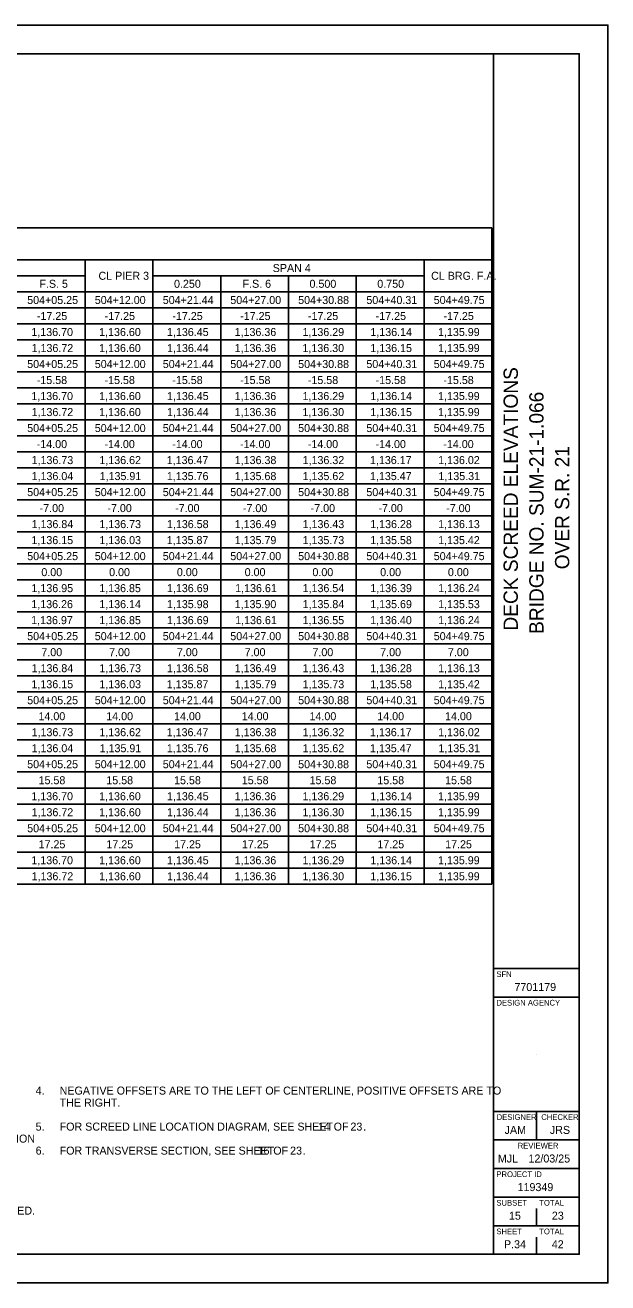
# Model space of a CAD drawing. Extents: x 0 to 34, y 0 to 22.
# Drawn here: x 23.8 to 34, y 0 to 22 of the extents above; entities that cross this region are included whole.
import ezdxf

# ---------------------------------------------------------------- set-up
doc = ezdxf.new("R2010")
doc.units = 0
for name, color, linetype in [('BR_P_Gen_Text', 7, 'Continuous'), ('Default', 7, 'Continuous'), ('SH_Border', 7, 'Continuous'), ('SH_Cut_Line', 7, 'Continuous'), ('SH_Data', 7, 'Continuous')]:
    doc.layers.add(name, color=color, linetype=linetype)

msp = doc.modelspace()

# ---------------------------------------------------------------- linework, layer by layer
at = {"layer": 'Default'}
for p, q in [((1.531, 18.456), (31.969, 18.456)), ((31.969, 18.456), (31.969, 6.976)), ((1.531, 17.896), (31.969, 17.896)), ((24.854, 17.896), (24.854, 6.976)), ((26.039, 17.896), (26.039, 6.976)), ((30.783, 17.896), (30.783, 6.976)), ((18.924, 17.616), (24.854, 17.616)), ((26.039, 17.616), (30.783, 17.616)), ((27.225, 17.616), (27.225, 6.976)), ((28.411, 17.616), (28.411, 6.976)), ((29.597, 17.616), (29.597, 6.976)), ((1.531, 17.336), (31.969, 17.336)), ((2.585, 17.056), (31.969, 17.056)), ((2.585, 16.776), (31.969, 16.776)), ((2.585, 16.496), (31.969, 16.496)), ((1.531, 16.216), (31.969, 16.216)), ((2.585, 15.936), (31.969, 15.936)), ((2.585, 15.656), (31.969, 15.656)), ((2.585, 15.376), (31.969, 15.376)), ((1.531, 15.096), (31.969, 15.096)), ((2.585, 14.816), (31.969, 14.816)), ((2.585, 14.536), (31.969, 14.536)), ((2.585, 14.256), (31.969, 14.256)), ((1.531, 13.976), (31.969, 13.976)), ((2.585, 13.696), (31.969, 13.696)), ((2.585, 13.416), (31.969, 13.416)), ((2.585, 13.136), (31.969, 13.136)), ((1.531, 12.856), (31.969, 12.856)), ((2.585, 12.576), (31.969, 12.576)), ((2.585, 12.296), (31.969, 12.296)), ((2.585, 12.016), (31.969, 12.016)), ((2.585, 11.736), (31.969, 11.736)), ((1.531, 11.456), (31.969, 11.456)), ((2.585, 11.176), (31.969, 11.176)), ((2.585, 10.896), (31.969, 10.896)), ((2.585, 10.616), (31.969, 10.616)), ((1.531, 10.336), (31.969, 10.336)), ((2.585, 10.056), (31.969, 10.056)), ((2.585, 9.776), (31.969, 9.776)), ((2.585, 9.496), (31.969, 9.496)), ((1.531, 9.216), (31.969, 9.216)), ((2.585, 8.936), (31.969, 8.936)), ((2.585, 8.656), (31.969, 8.656)), ((2.585, 8.376), (31.969, 8.376)), ((1.531, 8.096), (31.969, 8.096)), ((2.585, 7.816), (31.969, 7.816)), ((2.585, 7.536), (31.969, 7.536)), ((2.585, 7.256), (31.969, 7.256)), ((1.531, 6.976), (31.969, 6.976))]:
    msp.add_line(p, q, dxfattribs=at)
at = {"layer": 'SH_Border'}
for p, q in [((32, 0.5), (32, 21.5)), ((32, 5.5), (33.5, 5.5)), ((32, 5), (33.5, 5)), ((32, 3), (33.5, 3)), ((32.75, 3), (32.75, 2.5)), ((32, 2.5), (33.5, 2.5)), ((32, 2), (33.5, 2)), ((32, 1.5), (33.5, 1.5)), ((32, 1), (33.5, 1))]:
    msp.add_line(p, q, dxfattribs=at)
msp.add_lwpolyline([(1.5, 21.5), (33.5, 21.5), (33.5, 0.5), (1.5, 0.5)], close=True, dxfattribs=at)
at = {"layer": 'SH_Cut_Line'}
msp.add_lwpolyline([(0, 0), (34, 0), (34, 22), (0, 22)], close=True, dxfattribs=at)
at = {"layer": 'SH_Data'}
for p, q in [((32.75, 4), (32.75, 4)), ((32.75, 1), (32.75, 1.3)), ((32.375, 0.675), (32.375, 0.675)), ((32.75, 0.5), (32.75, 0.8))]:
    msp.add_line(p, q, dxfattribs=at)

# ---------------------------------------------------------------- texts
at = {"layer": 'BR_P_Gen_Text'}
for s, p in [('4.', (23.986, 3.293)), ('NEGATIVE OFFSETS ARE TO THE LEFT OF CENTERLINE, POSITIVE OFFSETS ARE TO ', (24.406, 3.293)), ('THE RIGHT.', (24.406, 3.083)), ('5.', (23.986, 2.663)), ('FOR SCREED LINE LOCATION DIAGRAM, SEE SHEET ', (24.406, 2.663)), ('14', (28.926, 2.663)), (' OF ', (29.15, 2.663)), ('23', (29.495, 2.663)), ('.', (29.718, 2.663)), ('TOP OF HAUNCH ELEVATIONS SHOWN REPRESENT THE THEORETICAL LOCATION ', (16.434, 2.453)), ('6.', (23.986, 2.243)), ('FOR TRANSVERSE SECTION, SEE SHEET', (24.406, 2.243)), ('16', (27.87, 2.243)), (' OF ', (28.093, 2.243)), ('23', (28.439, 2.243)), ('.', (28.662, 2.243)), ('LOCATION AFTER ALL ANTICIPATED DEAD LOAD DEFLECTIONS HAVE OCCURRED.', (16.434, 1.193))]:
    msp.add_text(s, height=0.14, dxfattribs=at).set_placement(p)
at = {"layer": 'Default'}
for s, p in [('SPAN 4', (28.135, 17.682)), ('CL PIER 3', (25.086, 17.546)), ('CL BRG. F.A.', (30.907, 17.546)), ('F.S. 5', (24.052, 17.406)), ('0.250', (26.408, 17.406)), ('F.S. 6', (27.607, 17.406)), ('0.500', (28.779, 17.406)), ('0.750', (29.965, 17.406)), ('504+05.25', (23.838, 17.122)), ('504+12.00', (25.021, 17.122)), ('504+21.44', (26.211, 17.122)), ('504+27.00', (27.393, 17.122)), ('504+30.88', (28.58, 17.122)), ('504+40.31', (29.774, 17.122)), ('504+49.75', (30.953, 17.122)), ('-17.25', (24.008, 16.842)), ('-17.25', (25.194, 16.842)), ('-17.25', (26.379, 16.842)), ('-17.25', (27.565, 16.842)), ('-17.25', (28.751, 16.842)), ('-17.25', (29.937, 16.842)), ('-17.25', (31.123, 16.842)), ('1,136.70', (23.911, 16.562)), ('1,136.60', (25.097, 16.562)), ('1,136.45', (26.285, 16.562)), ('1,136.36', (27.468, 16.562)), ('1,136.29', (28.656, 16.562)), ('1,136.14', (29.844, 16.562)), ('1,135.99', (31.028, 16.562)), ('1,136.72', (23.915, 16.282)), ('1,136.60', (25.097, 16.282)), ('1,136.44', (26.286, 16.282)), ('1,136.36', (27.468, 16.282)), ('1,136.30', (28.655, 16.282)), ('1,136.15', (29.843, 16.282)), ('1,135.99', (31.028, 16.282)), ('504+05.25', (23.838, 16.002)), ('504+12.00', (25.021, 16.002)), ('504+21.44', (26.211, 16.002)), ('504+27.00', (27.393, 16.002)), ('504+30.88', (28.58, 16.002)), ('504+40.31', (29.774, 16.002)), ('504+49.75', (30.953, 16.002)), ('-15.58', (24.006, 15.722)), ('-15.58', (25.192, 15.722)), ('-15.58', (26.378, 15.722)), ('-15.58', (27.564, 15.722)), ('-15.58', (28.75, 15.722)), ('-15.58', (29.936, 15.722)), ('-15.58', (31.122, 15.722)), ('1,136.70', (23.911, 15.442)), ('1,136.60', (25.097, 15.442)), ('1,136.45', (26.285, 15.442)), ('1,136.36', (27.468, 15.442)), ('1,136.29', (28.656, 15.442)), ('1,136.14', (29.844, 15.442)), ('1,135.99', (31.028, 15.442)), ('1,136.72', (23.915, 15.162)), ('1,136.60', (25.097, 15.162)), ('1,136.44', (26.286, 15.162)), ('1,136.36', (27.468, 15.162)), ('1,136.30', (28.655, 15.162)), ('1,136.15', (29.843, 15.162)), ('1,135.99', (31.028, 15.162)), ('504+05.25', (23.838, 14.882)), ('504+12.00', (25.021, 14.882)), ('504+21.44', (26.211, 14.882)), ('504+27.00', (27.393, 14.882)), ('504+30.88', (28.58, 14.882)), ('504+40.31', (29.774, 14.882)), ('504+49.75', (30.953, 14.882)), ('-14.00', (24.005, 14.602)), ('-14.00', (25.191, 14.602)), ('-14.00', (26.377, 14.602)), ('-14.00', (27.563, 14.602)), ('-14.00', (28.749, 14.602)), ('-14.00', (29.935, 14.602)), ('-14.00', (31.121, 14.602)), ('1,136.73', (23.915, 14.322)), ('1,136.62', (25.101, 14.322)), ('1,136.47', (26.28, 14.322)), ('1,136.38', (27.47, 14.322)), ('1,136.32', (28.658, 14.322)), ('1,136.17', (29.837, 14.322)), ('1,136.02', (31.03, 14.322)), ('1,136.04', (23.915, 14.042)), ('1,135.91', (25.106, 14.042)), ('1,135.76', (26.282, 14.042)), ('1,135.68', (27.47, 14.042)), ('1,135.62', (28.658, 14.042)), ('1,135.47', (29.837, 14.042)), ('1,135.31', (31.035, 14.042)), ('504+05.25', (23.838, 13.762)), ('504+12.00', (25.021, 13.762)), ('504+21.44', (26.211, 13.762)), ('504+27.00', (27.393, 13.762)), ('504+30.88', (28.58, 13.762)), ('504+40.31', (29.774, 13.762)), ('504+49.75', (30.953, 13.762)), ('-7.00', (24.056, 13.482)), ('-7.00', (25.242, 13.482)), ('-7.00', (26.427, 13.482)), ('-7.00', (27.613, 13.482)), ('-7.00', (28.799, 13.482)), ('-7.00', (29.985, 13.482)), ('-7.00', (31.171, 13.482)), ('1,136.84', (23.915, 13.202)), ('1,136.73', (25.101, 13.202)), ('1,136.58', (26.284, 13.202)), ('1,136.49', (27.47, 13.202)), ('1,136.43', (28.658, 13.202)), ('1,136.28', (29.841, 13.202)), ('1,136.13', (31.03, 13.202)), ('1,136.15', (23.913, 12.922)), ('1,136.03', (25.101, 12.922)), ('1,135.87', (26.28, 12.922)), ('1,135.79', (27.47, 12.922)), ('1,135.73', (28.658, 12.922)), ('1,135.58', (29.841, 12.922)), ('1,135.42', (31.03, 12.922)), ('504+05.25', (23.838, 12.642)), ('504+12.00', (25.021, 12.642)), ('504+21.44', (26.211, 12.642)), ('504+27.00', (27.393, 12.642)), ('504+30.88', (28.58, 12.642)), ('504+40.31', (29.774, 12.642)), ('504+49.75', (30.953, 12.642)), ('0.00', (24.086, 12.362)), ('0.00', (25.272, 12.362)), ('0.00', (26.458, 12.362)), ('0.00', (27.644, 12.362)), ('0.00', (28.83, 12.362)), ('0.00', (30.016, 12.362)), ('0.00', (31.201, 12.362)), ('1,136.95', (23.913, 12.082)), ('1,136.85', (25.099, 12.082)), ('1,136.69', (26.284, 12.082)), ('1,136.61', (27.478, 12.082)), ('1,136.54', (28.658, 12.082)), ('1,136.39', (29.842, 12.082)), ('1,136.24', (31.03, 12.082)), ('1,136.26', (23.91, 11.802)), ('1,136.14', (25.1, 11.802)), ('1,135.98', (26.284, 11.802)), ('1,135.90', (27.469, 11.802)), ('1,135.84', (28.658, 11.802)), ('1,135.69', (29.842, 11.802)), ('1,135.53', (31.03, 11.802)), ('1,136.97', (23.908, 11.522)), ('1,136.85', (25.099, 11.522)), ('1,136.69', (26.284, 11.522)), ('1,136.61', (27.478, 11.522)), ('1,136.55', (28.657, 11.522)), ('1,136.40', (29.84, 11.522)), ('1,136.24', (31.03, 11.522)), ('504+05.25', (23.838, 11.242)), ('504+12.00', (25.021, 11.242)), ('504+21.44', (26.211, 11.242)), ('504+27.00', (27.393, 11.242)), ('504+30.88', (28.58, 11.242)), ('504+40.31', (29.774, 11.242)), ('504+49.75', (30.953, 11.242)), ('7.00', (24.086, 10.962)), ('7.00', (25.272, 10.962)), ('7.00', (26.458, 10.962)), ('7.00', (27.644, 10.962)), ('7.00', (28.83, 10.962)), ('7.00', (30.016, 10.962)), ('7.00', (31.201, 10.962)), ('1,136.84', (23.915, 10.682)), ('1,136.73', (25.101, 10.682)), ('1,136.58', (26.284, 10.682)), ('1,136.49', (27.47, 10.682)), ('1,136.43', (28.658, 10.682)), ('1,136.28', (29.841, 10.682)), ('1,136.13', (31.03, 10.682)), ('1,136.15', (23.913, 10.402)), ('1,136.03', (25.101, 10.402)), ('1,135.87', (26.28, 10.402)), ('1,135.79', (27.47, 10.402)), ('1,135.73', (28.658, 10.402)), ('1,135.58', (29.841, 10.402)), ('1,135.42', (31.03, 10.402)), ('504+05.25', (23.838, 10.122)), ('504+12.00', (25.021, 10.122)), ('504+21.44', (26.211, 10.122)), ('504+27.00', (27.393, 10.122)), ('504+30.88', (28.58, 10.122)), ('504+40.31', (29.774, 10.122)), ('504+49.75', (30.953, 10.122)), ('14.00', (24.036, 9.842)), ('14.00', (25.222, 9.842)), ('14.00', (26.408, 9.842)), ('14.00', (27.593, 9.842)), ('14.00', (28.779, 9.842)), ('14.00', (29.965, 9.842)), ('14.00', (31.151, 9.842)), ('1,136.73', (23.915, 9.562)), ('1,136.62', (25.101, 9.562)), ('1,136.47', (26.28, 9.562)), ('1,136.38', (27.47, 9.562)), ('1,136.32', (28.658, 9.562)), ('1,136.17', (29.837, 9.562)), ('1,136.02', (31.03, 9.562)), ('1,136.04', (23.915, 9.282)), ('1,135.91', (25.106, 9.282)), ('1,135.76', (26.282, 9.282)), ('1,135.68', (27.47, 9.282)), ('1,135.62', (28.658, 9.282)), ('1,135.47', (29.837, 9.282)), ('1,135.31', (31.035, 9.282)), ('504+05.25', (23.838, 9.002)), ('504+12.00', (25.021, 9.002)), ('504+21.44', (26.211, 9.002)), ('504+27.00', (27.393, 9.002)), ('504+30.88', (28.58, 9.002)), ('504+40.31', (29.774, 9.002)), ('504+49.75', (30.953, 9.002)), ('15.58', (24.037, 8.722)), ('15.58', (25.223, 8.722)), ('15.58', (26.409, 8.722)), ('15.58', (27.594, 8.722)), ('15.58', (28.78, 8.722)), ('15.58', (29.966, 8.722)), ('15.58', (31.152, 8.722)), ('1,136.70', (23.911, 8.442)), ('1,136.60', (25.097, 8.442)), ('1,136.45', (26.285, 8.442)), ('1,136.36', (27.468, 8.442)), ('1,136.29', (28.656, 8.442)), ('1,136.14', (29.844, 8.442)), ('1,135.99', (31.028, 8.442)), ('1,136.72', (23.915, 8.162)), ('1,136.60', (25.097, 8.162)), ('1,136.44', (26.286, 8.162)), ('1,136.36', (27.468, 8.162)), ('1,136.30', (28.655, 8.162)), ('1,136.15', (29.843, 8.162)), ('1,135.99', (31.028, 8.162)), ('504+05.25', (23.838, 7.882)), ('504+12.00', (25.021, 7.882)), ('504+21.44', (26.211, 7.882)), ('504+27.00', (27.393, 7.882)), ('504+30.88', (28.58, 7.882)), ('504+40.31', (29.774, 7.882)), ('504+49.75', (30.953, 7.882)), ('17.25', (24.038, 7.602)), ('17.25', (25.224, 7.602)), ('17.25', (26.41, 7.602)), ('17.25', (27.596, 7.602)), ('17.25', (28.782, 7.602)), ('17.25', (29.967, 7.602)), ('17.25', (31.153, 7.602)), ('1,136.70', (23.911, 7.322)), ('1,136.60', (25.097, 7.322)), ('1,136.45', (26.285, 7.322)), ('1,136.36', (27.468, 7.322)), ('1,136.29', (28.656, 7.322)), ('1,136.14', (29.844, 7.322)), ('1,135.99', (31.028, 7.322)), ('1,136.72', (23.915, 7.042)), ('1,136.60', (25.097, 7.042)), ('1,136.44', (26.286, 7.042)), ('1,136.36', (27.468, 7.042)), ('1,136.30', (28.655, 7.042)), ('1,136.15', (29.843, 7.042)), ('1,135.99', (31.028, 7.042))]:
    msp.add_text(s, height=0.14, dxfattribs=at).set_placement(p)
at = {"layer": 'SH_Data'}
for s, p in [('DECK SCREED ELEVATIONS', (32.425, 11.41)), ('BRIDGE NO. SUM-21-1.066', (32.875, 11.352)), ('OVER S.R. 21', (33.325, 12.482))]:
    msp.add_text(s, height=0.25, rotation=90, dxfattribs=at).set_placement(p)
for s, height, p in [('SFN', 0.1, (32.05, 5.35)), ('7701179', 0.14, (32.365, 5.105)), ('DESIGN AGENCY', 0.1, (32.05, 4.85)), ('DESIGNER', 0.1, (32.054, 2.85)), ('CHECKER', 0.1, (32.835, 2.85)), ('JAM', 0.14, (32.193, 2.605)), ('JRS', 0.14, (32.985, 2.605)), ('REVIEWER', 0.1, (32.422, 2.35)), ('MJL', 0.14, (32.075, 2.105)), ('12/03/25', 0.14, (32.611, 2.105)), ('PROJECT ID', 0.1, (32.05, 1.85)), ('119349', 0.14, (32.42, 1.605)), ('SUBSET', 0.1, (32.05, 1.35)), ('TOTAL', 0.1, (32.8, 1.35)), ('15', 0.14, (32.27, 1.105)), ('23', 0.14, (33.02, 1.105)), ('SHEET', 0.1, (32.05, 0.85)), ('TOTAL', 0.1, (32.8, 0.85)), ('P.34', 0.14, (32.182, 0.605)), ('42', 0.14, (33.019, 0.605))]:
    msp.add_text(s, height=height, dxfattribs=at).set_placement(p)

doc.saveas('drawing.dxf')
